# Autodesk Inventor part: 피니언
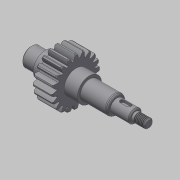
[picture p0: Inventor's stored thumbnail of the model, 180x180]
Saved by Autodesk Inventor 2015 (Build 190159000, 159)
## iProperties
Created: 2019-06
Part Number: 피니언
Material: 스테인리스강
Document SubType Name: Modeling
Designer: mduedu
Density: 8.08 g/cm^3
Appearance: 기본값
Mass: 336.303 g
Surface Area: 112.617 cm^2
Volume: 41.6216 cm^3
Author: mduedu
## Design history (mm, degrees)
sketch "스케치1"
  geometry: L1 (0, 0)-(13, 0); L2 (13, 0)-(13, 8.5); L3 (13, 8.5)-(0, 8.5); L4 (0, 8.5)-(0, 0); L5 (13, 0)-(53, 0); L6 (53, 0)-(53, 11); L7 (53, 11)-(13, 11); L8 (13, 11)-(13, 0); L9 (53, 0)-(78, 0); L10 (78, 0)-(78, 8.5); L11 (78, 8.5)-(53, 8.5); L12 (53, 8.5)-(53, 0); L13 (78, 0)-(95, 0); L14 (95, 0)-(95, 6); L15 (95, 6)-(78, 6); L16 (78, 6)-(78, 0); L17 (95, 0)-(107, 0); L18 (107, 0)-(107, 4); L19 (107, 4)-(95, 4); L20 (95, 4)-(95, 0)
  constraints: 40 end point, 10 parallel, 5 horizontal, 5 perpendicular
  dimensions: "d0" = 107 distance between parallel lines of L18 L4; "d2" = 78 distance between parallel lines of L10 L4; "d3" = 40 distance of L6.end L7.end; "d4" = 25 distance of L10.end L11.end; "d5" = 17 distance of L14.end L15.end; "d6" = 8 diameter of L19 L17; "d7" = 12 diameter of L15 L13; "d8" = 17 diameter of L11 L9; "d9" = 22 diameter of L7 L5; "d10" = 17 diameter of L3 L1
revolve "회전1" sketch "스케치1" stored, may be unused: angle "d11" = 90 deg
node "작업 평면1"
sketch "스케치2"
  geometry: C1 r 17.5 at (0, 0); C2 r 20 at (0, 0); C3 r 22 at (0, 0); 1 further point
  constraints: 3 centre point, 3 coincident
  dimensions: "d13" = 40 diameter of C2; "d15" = 44 diameter of C3; "d16" = 35 diameter of C1
extrude "돌출1" join sketch "스케치2" distance "d17" = 18; taper "d18" = 0 deg
sketch "스케치3"
  geometry: L1 (0, 0)-(22, 0); L2 (0, 0)-(0, 22); L3 (0.57, 0)-(0.57, 22); L4 (1.57, 0)-(1.57, 22); L5 (2.07, 0)-(2.07, 22); A1 r 22 centre (0, 0) between (22, 0) and (0, 22) reference; A2 r 9.495 centre (-7.411, 16.856) between (2.07, 17.377) and (0.57, 22); A3 r 9.495 centre (7.411, 16.856) between (-0.57, 22) and (-2.07, 17.377); A4 r 17.5 centre (0, 0) between (2.07, 17.377) and (-2.07, 17.377); A5 r 22.007 centre (0, 0) between (0.57, 22) and (-0.57, 22); 4 further points
  constraints: 11 point on circle, 10 end point, 6 parallel, 5 point on line, 4 centre point, 3 symmetric about line, 2 coincident, 1 horizontal, 1 perpendicular, 5 other
  dimensions: "d19" = 0.5 distance between parallel lines of L5 L4; "d21" = 1 distance between parallel lines of L3 L4; "d22" = 1.57 distance between parallel lines of L2 L4
extrude "돌출2" join sketch "스케치3" stored distance "d23" = 18; taper "d24" = 0 deg
chamfer "모따기1" distance "d25" = 1; stored, may be unused: second distance "d26" = 2, angle "d27" = 45 deg
fillet "모깎기1" dims "d31" = 0.3
chamfer "모따기2" distance "d32" = 1; stored, may be unused: second distance "d33" = 2, angle "d34" = 45 deg
node "작업 평면2"
sketch "스케치4"
  geometry: L1 (3.5, -2)-(-2.5, -2); L2 (-2.5, 2)-(3.5, 2); L3 (8.5, 8.5)-(8.5, -8.5) reference; A1 r 2 centre (3.5, 0) between (3.5, -2) and (3.5, 2); A2 r 2 centre (-2.5, 0) between (-2.5, 2) and (-2.5, -2); 1 further point
  constraints: 4 end point, 4 point on circle, 4 tangent, 2 centre point, 1 horizontal, 1 horizontal alignment, 1 parallel
  dimensions: "d35" = 3 distance edge to line of A1 L3; "d36" = 10 dimension on A2 A1; "d37" = 4 distance between parallel lines of L2 L1
extrude "돌출3" cut sketch "스케치4" distance "d38" = 2.5; taper "d39" = 0 deg
chamfer "모따기3" distance "d40" = 1.82; stored, may be unused: second distance "d41" = 2, angle "d42" = 30 deg
fillet "모깎기2" dims "d43" = 1, "d44" = 2
chamfer "모따기4" distance "d45" = 1; stored, may be unused: second distance "d46" = 2, angle "d47" = 30 deg
feature "스레드1" dims "d48" = 10, "d49" = 0
chamfer "모따기5" distance "d50" = 1; stored, may be unused: second distance "d51" = 2, angle "d52" = 30 deg
node "솔리드1"
pattern_circular "원형 패턴1" dims angle "d29" = 360 deg
other parameters: "d12" = -12
